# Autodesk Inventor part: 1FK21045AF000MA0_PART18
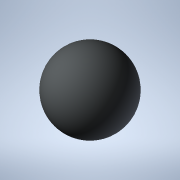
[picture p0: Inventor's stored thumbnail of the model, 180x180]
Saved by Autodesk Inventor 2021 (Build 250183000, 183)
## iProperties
Created: 2025-04
Part Number: 1FK21045AF000MA0_PART18
Material: Generic
Catalog Web Link: www.3dfindit.com
Description: -Servo synchronous motor
Document SubType Name: Modeling
Designer: psAdmin
Mass: 0.137258 g
Surface Area: 1.2868 cm^2
Volume: 0.137258 cm^3
Density: 1 g/cm^3
Appearance: PSOLRGB-212-217-219
Category: PARTsolutions
Title: 1FK21045AF000MA0_PART18
Author: Cadenas PARTsolutions
Comments: Servo synchronous motor
Sending System: PARTsolutions
Preprocessor: ST-DEVELOPER v19.3
PSOL_IDENT_0: {$CADENAS_DATA/23d-libs/siemens_ag/_cat_/8b/0a/1fk21045af000ma0.prj},216 {VTYP=3D},{NB=1FK21045AF000
PSOL_IDENT_1: MA0_PART18},{LINA=1FK21045AF000MA0_PART18},{NN=1FK21045AF000MA0_PART18},{NOPRJ=TRUE},{DATE=19.08.202
PSOL_IDENT_2: 5 14:00:48},{GEOMDATE=30.07.2025 02:00:28},{VERSION=},{LINEID=10},{WBVAR=},{WBNUMERIC=}  {NB=1FK2104
PSOL_IDENT_3: 5AF000MA0_PART18},{LINA=1FK21045AF000MA0_PART18},{KT=DUMMY},{PREVIEW=../../../_pool_/a9/69/p_d211_xx
PSOL_IDENT_4: _00818j.png},{DESCSHORT=SIMOTICS S-1FK2 HD, SINAMICS S210 3AC 400V-480V, 2.4 Nm, 3000 rpm},{DESCLONG=
PSOL_IDENT_5: SIMOTICS S-1FK2 HD servo motor M0=2.4 Nm; PN = 0.75 kW at nN=3000 rpm (380-480 V); PN = 0.375 kW at
PSOL_IDENT_6: nN=1500 rpm (200-240 V); degree of protection IP64; cylindrical shaft D19x40mm; absolute encoder 22-
PSOL_IDENT_7: bit + 12-bit multiturn (encoder AM22DQC); with OCC interface; plug size M17, rotatable; SIMOTICS S-1
PSOL_IDENT_8: FK2 servomotorfor a wide range of uses in industrial environments. SIMOTICS S‑1FK2 servomotors are c
PSOL_IDENT_9: ompact synchronous motors with a high dynamic performance that set themselves apart as a result of t
PSOL_IDENT_10: heir high power density, degree of protection and overload capability. The motors are available in t
PSOL_IDENT_11: wo variants: as High Dynamic variant (highest dynamic performance as a result of the low intrinsic m
PSOL_IDENT_12: oment of inertia for applications demanding a high dynamic performance with low moved masses) - and
PSOL_IDENT_13: as Compact variant (precise and stable closed-loop control for medium up to large moved masses as a
PSOL_IDENT_14: result of a medium intrinsic moment of inertia). SIMOTICSS‑1FK2 servomotors fully exploit their stre
PSOL_IDENT_15: ngths in a system with the SINAMICSS210 frequency converter and simple connection using the one cabl
PSOL_IDENT_16: e connection (OCC). Advantages include the short control and positioning times, fast and precise cor
PSOL_IDENT_17: rection of disturbing quantities as well as stable control with a high dynamic performance. The serv
PSOL_IDENT_18: o motors can be configured to address a wide range of requirements. For example with and without hol
PSOL_IDENT_19: ding brake, IP64 or IP65 degree of protection, singleturn or multiturn absolute encoders - to name j
PSOL_IDENT_20: ust a few. Further, the servomotors are available in different shaft heights extending from 20 to 10
PSOL_IDENT_21: 0. A shaft sealing ring is available to achieve an IP65 degree of protection and for subsequent moun
PSOL_IDENT_22: ting at the motor or as spare part. SIMOTICS - the optimum motor for each and every motion control a
PSOL_IDENT_23: pplication.},{INTNO=195125050112},{SUPPLIERALTNO=1FK2104-5AF00-0MA0},{MANUID=1FK21045AF000MA0},{MANU
PSOL_IDENT_24: NAME=Siemens},{MANUTYPEDESC=Synchronous motor 1FK2-HD 2.4 NM},{AAU732=SIMOTICS},{AAO057=S-1FK2},{AAU
PSOL_IDENT_25: 734=SIMOTICS S-1FK2 HD servo motor M0=2.4 Nm; PN = 0.75 kW at nN=3000 rpm (380-480 V); PN = 0.375 kW
PSOL_IDENT_26: at nN=1500 rpm (200-240 V); degree of protection IP64; cylindrical shaft D19x40mm; absolute encoder
PSOL_IDENT_27: 22-bit + 12-bit multiturn (encoder AM22DQC); with OCC interface; plug size M17, rotatable;},{AAW338=
PSOL_IDENT_28: Synchronous motor 1FK2-HD 2.4 NM},{AAO742=SIMOTICS},{AAO663=4042948692912},{NOCUPEROU=1},{PRICEQUANT
PSOL_IDENT_29: ITY=1},{QUANTITYMIN=1},{QUANTITYINT=1},{CTN=85015100},{COO=DE},{AAO676=1FK2104-5AF00-0MA0},{AAO677=S
PSOL_IDENT_30: iemens AG},{ORDERUNIT=C62},{CONTENTUNIT=C62}
NB: 1FK21045AF000MA0_PART18
NT: Servo synchronous motor
NBSYN: $MANUID._PART18
LINA: 1FK21045AF000MA0_PART18
CATALOG: SIEMENS
PREVIEW: ../../../_pool_/a9/69/p_d211_xx_00818j.png
DESCSHORT: SIMOTICS S-1FK2 HD, SINAMICS S210 3AC 400V-480V, 2.4 Nm, 3000 rpm
DESCLONG: SIMOTICS S-1FK2 HD servo motor M0=2.4 Nm; PN = 0.75 kW at nN=3000 rpm (380-480 V); PN = 0.375 kW at nN=1500 rpm (200-240 V); degree of protection IP64; cylindri
INTNO: 195125050112
SUPPLIERALTNO: 1FK2104-5AF00-0MA0
MANUID: 1FK21045AF000MA0
MANUNAME: Siemens
MANUTYPEDESC: Synchronous motor 1FK2-HD 2.4 NM
AAU732: SIMOTICS
AAO057: S-1FK2
AAU734: SIMOTICS S-1FK2 HD servo motor M0=2.4 Nm; PN = 0.75 kW at nN=3000 rpm (380-480 V); PN = 0.375 kW at nN=1500 rpm (200-240 V); degree of protection IP64; cylindri
AAW338: Synchronous motor 1FK2-HD 2.4 NM
AAO742: SIMOTICS
AAO663: 4042948692912.0
NOCUPEROU: 1
PRICEQUANTITY: 1
QUANTITYMIN: 1
QUANTITYINT: 1
CTN: 85015100
COO: DE
ARTICLENO: 1FK21045AF000MA0_PART18
BOMINFO: 1FK21045AF000MA0_PART18
CREATOR: CADENAS GmbH
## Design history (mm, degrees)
feature "2025_04_17_15_40_42_0766"
body "Solid1"
